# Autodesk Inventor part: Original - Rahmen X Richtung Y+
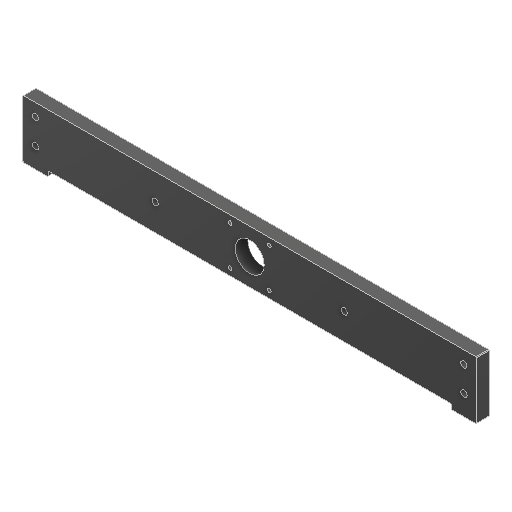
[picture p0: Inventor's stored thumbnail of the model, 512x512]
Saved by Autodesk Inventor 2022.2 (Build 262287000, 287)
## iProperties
Created: 2024-09
Part Number: Original - Rahmen X Richtung Y+
Material: Generico
Document SubType Name: Modeling
Designer: 18907419
Density: 1 g/cm^3
Appearance: Default
Author: 18907419
Revision Number: ANY
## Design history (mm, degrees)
feature "Aufsatz-Linear austragen1"
node "Solido1"
